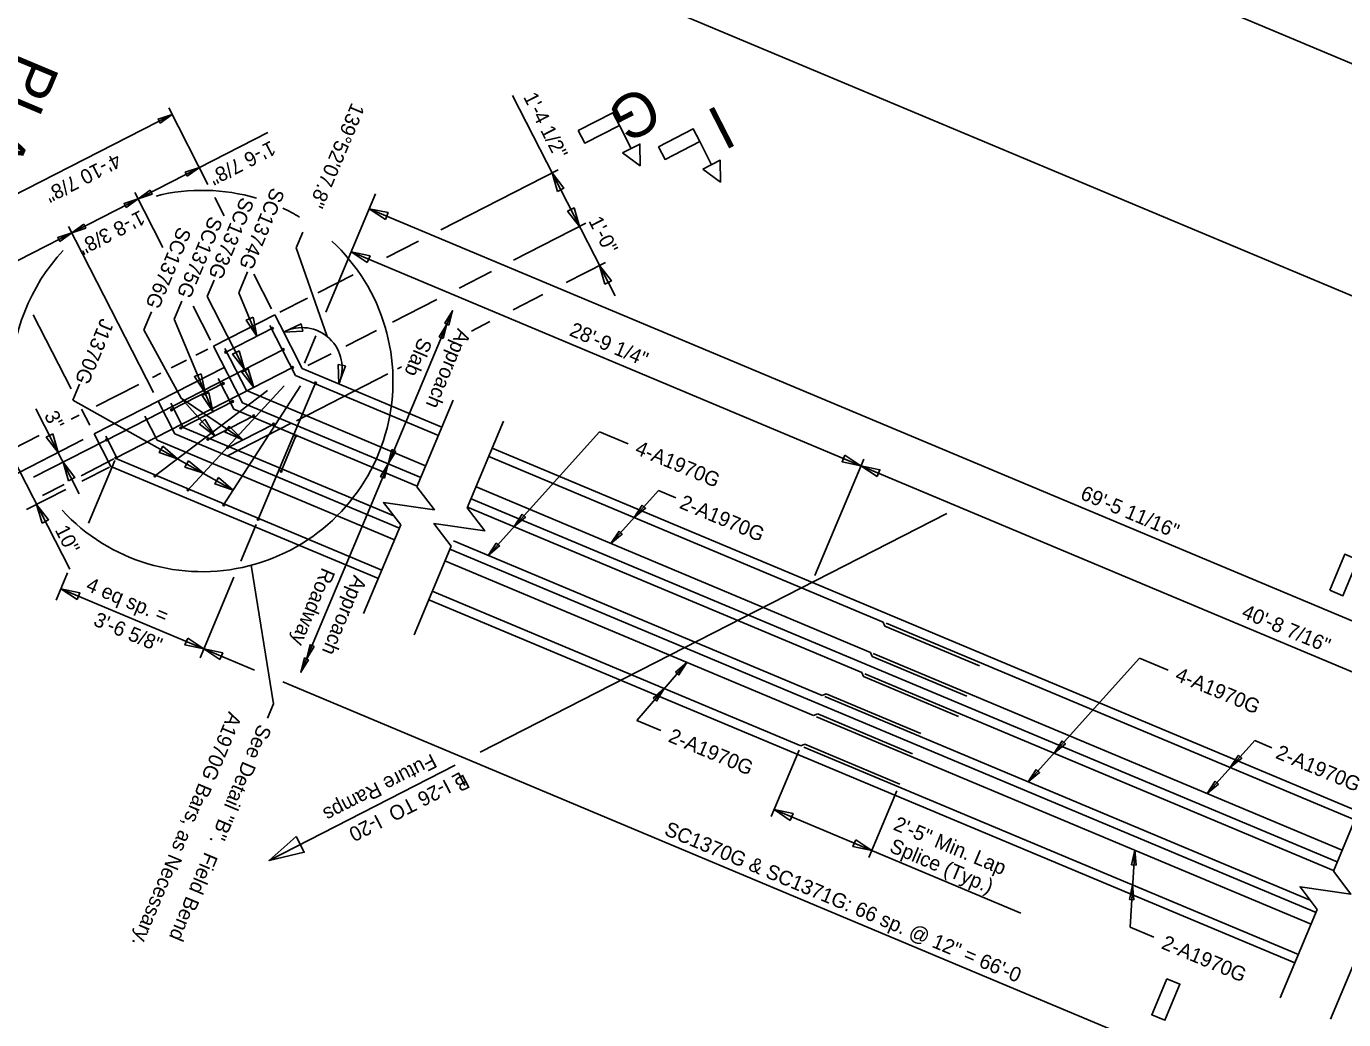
# Model space of a CAD drawing. Extents: x 1968564 to 1968711, y 796599 to 796794.
# Drawn here: x 1968616.17 to 1968661.26, y 796715.41 to 796749.41 of the extents above; entities that cross this region are included whole.
import ezdxf

# ---------------------------------------------------------------- set-up
doc = ezdxf.new("R2010")
doc.units = 0
for name, color, linetype in [('BR_AUTO DIMENSION', 7, 'Continuous'), ('BR_BORDER LINES', 7, 'Continuous'), ('BR_CENTER LINES', 7, 'Continuous'), ('BR_CONCRETE', 7, 'Continuous'), ('BR_REBAR', 7, 'Continuous'), ('BR_TABLE LINES', 7, 'Continuous'), ('BR_TEXT', 7, 'Continuous'), ('Default', 7, 'Continuous'), ('Level 31', 7, 'Continuous')]:
    doc.layers.add(name, color=color, linetype=linetype)

# ---------------------------------------------------------------- blocks, each defined once
blk = doc.blocks.new('B')
at = {"layer": 'BR_AUTO DIMENSION'}
blk.add_lwpolyline([(-0.2, 0.03), (0, 0), (-0.2, -0.03)], close=True, dxfattribs=at)
blk = doc.blocks.new('ARROW')
at = {"layer": 'BR_AUTO DIMENSION', "xscale": 0.625, "yscale": 0.625}
blk.add_blockref('B', (0, 0), dxfattribs=at)
blk = doc.blocks.new('DAH')
at = {"layer": 'BR_AUTO DIMENSION'}
for p in [(-0.125, 0), (0, 0)]:
    blk.add_blockref('ARROW', p, dxfattribs=at)

msp = doc.modelspace()

# ---------------------------------------------------------------- linework, layer by layer
at = {"layer": 'BR_AUTO DIMENSION'}
for p, q in [((1968632.811, 796747.035), (1968636.321, 796740.18)), ((1968621.161, 796746.392), (1968614.613, 796743.039)), ((1968622.387, 796743.998), (1968621.047, 796746.615)), ((1968624.441, 796745.776), (1968618.755, 796742.864)), ((1968630.363, 796742.444), (1968634.378, 796744.5)), ((1968620.849, 796741.833), (1968619.881, 796743.722)), ((1968626.425, 796739.628), (1968628.12, 796743.67)), ((1968622.941, 796742.917), (1968622.618, 796743.547)), ((1968618.755, 796742.864), (1968615.417, 796741.155)), ((1968627.909, 796743.166), (1968679.369, 796721.583)), ((1968620.525, 796736.874), (1968617.613, 796742.56)), ((1968625.638, 796742.358), (1968625.413, 796741.821)), ((1968632.85, 796741.401), (1968635.318, 796742.665)), ((1968625.413, 796741.821), (1968626.472, 796738.787)), ((1968628.499, 796741.49), (1968629.6, 796742.054)), ((1968627.287, 796741.685), (1968644.739, 796734.365)), ((1968623.44, 796740.288), (1968623.742, 796741.007)), ((1968624.568, 796739.74), (1968623.959, 796740.928)), ((1968630.987, 796740.447), (1968632.088, 796741.011)), ((1968634.652, 796740.639), (1968636.001, 796741.329)), ((1968622.362, 796740.156), (1968622.599, 796740.721)), ((1968626.15, 796740.288), (1968627.354, 796740.904)), ((1968623.954, 796737.047), (1968622.362, 796740.156)), ((1968623.44, 796740.288), (1968624.066, 796738.799)), ((1968624.851, 796739.622), (1968625.8, 796740.108)), ((1968628.7, 796739.276), (1968630.224, 796740.056)), ((1968632.837, 796739.709), (1968633.855, 796740.23)), ((1968620.19, 796739.02), (1968620.45, 796739.639)), ((1968621.232, 796739.38), (1968621.491, 796739.998)), ((1968622.47, 796738.666), (1968621.876, 796739.826)), ((1968627.835, 796732.698), (1968630.761, 796739.674)), ((1968617.708, 796736.995), (1968616.406, 796739.537)), ((1968621.232, 796739.38), (1968622.559, 796736.222)), ((1968631.406, 796738.976), (1968632.042, 796739.302)), ((1968620.19, 796739.02), (1968621.467, 796736.679)), ((1968625.693, 796737.883), (1968626.085, 796738.817)), ((1968627.105, 796738.459), (1968628.155, 796738.997)), ((1968622.389, 796738.362), (1968621.972, 796738.148)), ((1968621.653, 796737.985), (1968621.126, 796737.715)), ((1968625.806, 796737.794), (1968626.603, 796738.202)), ((1968620.77, 796737.532), (1968620.493, 796737.391)), ((1968625.415, 796735.909), (1968628.549, 796737.513)), ((1968628.88, 796737.683), (1968629.016, 796737.753)), ((1968614.48, 796737.033), (1968617.659, 796730.824)), ((1968617.766, 796736.612), (1968617.994, 796737.157)), ((1968620.027, 796737.152), (1968618.564, 796736.403)), ((1968623.256, 796733.532), (1968617.766, 796736.612)), ((1968623.584, 796735.252), (1968621.467, 796736.679)), ((1968621.467, 796736.679), (1968622.625, 796735.394)), ((1968629.538, 796733.648), (1968630.781, 796736.61)), ((1968616.495, 796736.316), (1968617.985, 796733.405)), ((1968617.977, 796736.102), (1968617.711, 796735.966)), ((1968618.342, 796735.756), (1968618.06, 796736.307)), ((1968631.262, 796732.925), (1968632.504, 796735.887)), ((1968635.791, 796735.532), (1968631.977, 796731.299)), ((1968636.771, 796735.121), (1968635.791, 796735.532)), ((1968616.605, 796735.4), (1968615.245, 796734.703)), ((1968618.118, 796735.262), (1968615.548, 796733.946)), ((1968618.854, 796735.217), (1968616.417, 796733.97)), ((1968619.171, 796734.598), (1968618.049, 796734.024)), ((1968619.018, 796734.318), (1968618.071, 796733.833)), ((1968619.197, 796734.541), (1968618.3, 796732.404)), ((1968643.163, 796730.607), (1968644.836, 796734.596)), ((1968643.163, 796730.607), (1968644.836, 796734.596)), ((1968644.739, 796734.365), (1968678.747, 796720.102)), ((1968617.469, 796733.727), (1968616.724, 796733.345)), ((1968617.521, 796733.552), (1968616.181, 796732.866)), ((1968637.811, 796733.517), (1968636.179, 796731.706)), ((1968638.402, 796733.269), (1968637.811, 796733.517)), ((1968624.037, 796732.36), (1968623.51, 796731.103)), ((1968625.569, 796727.295), (1968627.835, 796732.698)), ((1968627.717, 796729.306), (1968628.99, 796732.34)), ((1968629.441, 796728.583), (1968630.714, 796731.617)), ((1968617.584, 796730.696), (1968617.193, 796729.764)), ((1968623.279, 796730.553), (1968622.119, 796727.787)), ((1968623.867, 796730.958), (1968624.636, 796726.217)), ((1968622.249, 796728.098), (1968617.355, 796730.15)), ((1968622.249, 796728.098), (1968623.978, 796727.373)), ((1968637.07, 796725.647), (1968638.776, 796727.635)), ((1968654.277, 796727.779), (1968650.463, 796723.546)), ((1968655.258, 796727.368), (1968654.277, 796727.779)), ((1968624.948, 796726.966), (1968669, 796708.489)), ((1968624.636, 796726.217), (1968624.43, 796725.724)), ((1968637.888, 796725.304), (1968637.07, 796725.647)), ((1968658.217, 796724.959), (1968656.585, 796723.148)), ((1968658.808, 796724.711), (1968658.217, 796724.959)), ((1968642.626, 796724.635), (1968641.67, 796722.357)), ((1968660.909, 796720.49), (1968662.151, 796723.452)), ((1968645.968, 796723.233), (1968645.013, 796720.955)), ((1968641.77, 796722.595), (1968650.217, 796719.052)), ((1968653.95, 796718.567), (1968654.111, 796721.203)), ((1968659.088, 796716.149), (1968660.361, 796719.182)), ((1968654.768, 796718.224), (1968653.95, 796718.567)), ((1968660.812, 796715.426), (1968662.084, 796718.459))]:
    msp.add_line(p, q, dxfattribs=at)
for points in [[(1968620.75, 796746.098), (1968621.161, 796746.392), (1968620.682, 796746.231)], [(1968621.682, 796744.279), (1968622.093, 796744.573), (1968621.613, 796744.412)], [(1968634.35, 796743.756), (1968634.165, 796744.391), (1968634.572, 796743.87)], [(1968620.406, 796743.794), (1968619.995, 796743.499), (1968620.475, 796743.661)], [(1968619.585, 796743.205), (1968619.995, 796743.499), (1968619.516, 796743.338)], [(1968634.697, 796743.077), (1968635.105, 796742.556), (1968634.92, 796743.191)], [(1968628.46, 796742.8), (1968627.909, 796743.166), (1968628.556, 796743.03)], [(1968617.316, 796742.043), (1968617.727, 796742.338), (1968617.248, 796742.177)], [(1968618.138, 796742.633), (1968617.727, 796742.338), (1968618.206, 796742.499)], [(1968627.838, 796741.318), (1968627.287, 796741.685), (1968627.935, 796741.549)], [(1968635.973, 796740.585), (1968635.788, 796741.22), (1968636.196, 796740.699)], [(1968623.93, 796739.447), (1968624.066, 796738.799), (1968623.699, 796739.35)], [(1968625.637, 796738.977), (1968624.975, 796738.943), (1968625.577, 796739.219)], [(1968623.452, 796738.302), (1968623.637, 796737.666), (1968623.23, 796738.188)], [(1968627.097, 796737.791), (1968626.869, 796737.17), (1968626.85, 796737.831)], [(1968622.152, 796737.512), (1968622.289, 796736.865), (1968621.922, 796737.416)], [(1968623.769, 796737.683), (1968623.954, 796737.047), (1968623.547, 796737.569)], [(1968622.422, 796736.87), (1968622.559, 796736.222), (1968622.192, 796736.773)], [(1968622.283, 796735.961), (1968622.625, 796735.394), (1968622.097, 796735.793)], [(1968623.115, 796735.719), (1968623.584, 796735.252), (1968622.975, 796735.512)], [(1968617.074, 796735.458), (1968617.26, 796734.822), (1968616.852, 796735.343)], [(1968620.842, 796735.033), (1968621.346, 796734.604), (1968620.719, 796734.815)], [(1968628.823, 796734.859), (1968628.56, 796734.427), (1968628.684, 796734.917)], [(1968644.188, 796734.732), (1968644.739, 796734.365), (1968644.092, 796734.502)], [(1968617.612, 796733.852), (1968617.431, 796734.489), (1968617.836, 796733.965)], [(1968621.726, 796734.537), (1968622.23, 796734.108), (1968621.602, 796734.319)], [(1968628.436, 796733.937), (1968628.56, 796734.427), (1968628.297, 796733.995)], [(1968645.291, 796733.999), (1968644.739, 796734.365), (1968645.387, 796734.229)], [(1968622.752, 796733.961), (1968623.256, 796733.532), (1968622.629, 796733.743)], [(1968616.709, 796732.406), (1968616.524, 796733.041), (1968616.931, 796732.52)], [(1968637.256, 796733.013), (1968636.977, 796732.591), (1968637.367, 796732.913)], [(1968633.143, 796732.705), (1968632.864, 796732.283), (1968633.254, 796732.604)], [(1968636.458, 796732.128), (1968636.179, 796731.706), (1968636.569, 796732.027)], [(1968632.256, 796731.721), (1968631.977, 796731.299), (1968632.368, 796731.621)], [(1968617.906, 796729.784), (1968617.355, 796730.15), (1968618.003, 796730.014)], [(1968621.698, 796728.464), (1968622.249, 796728.098), (1968621.602, 796728.234)], [(1968622.8, 796727.731), (1968622.249, 796728.098), (1968622.897, 796727.961)], [(1968626.022, 796728.183), (1968625.76, 796727.751), (1968625.884, 796728.241)], [(1968625.831, 796727.727), (1968625.569, 796727.295), (1968625.693, 796727.786)], [(1968638.394, 796727.304), (1968638.776, 796727.635), (1968638.507, 796727.206)], [(1968637.624, 796726.407), (1968638.006, 796726.738), (1968637.738, 796726.309)], [(1968651.629, 796724.951), (1968651.35, 796724.53), (1968651.74, 796724.851)], [(1968657.662, 796724.454), (1968657.383, 796724.033), (1968657.773, 796724.354)], [(1968650.742, 796723.968), (1968650.463, 796723.546), (1968650.854, 796723.867)], [(1968656.864, 796723.569), (1968656.585, 796723.148), (1968656.975, 796723.469)], [(1968642.321, 796722.228), (1968641.77, 796722.595), (1968642.417, 796722.458)], [(1968644.561, 796721.559), (1968645.112, 796721.193), (1968644.465, 796721.329)], [(1968654.005, 796720.709), (1968654.111, 796721.203), (1968654.155, 796720.699)], [(1968653.933, 796719.519), (1968654.038, 796720.014), (1968654.083, 796719.51)]]:
    msp.add_lwpolyline(points, close=True, dxfattribs=at)
for points in [[(1968629.538, 796733.648), (1968630.14, 796732.859), (1968628.398, 796733.11), (1968628.99, 796732.34)], [(1968631.262, 796732.925), (1968631.864, 796732.136), (1968630.122, 796732.387), (1968630.714, 796731.617)], [(1968660.909, 796720.49), (1968661.511, 796719.702), (1968659.769, 796719.953), (1968660.361, 796719.182)]]:
    msp.add_lwpolyline(points, dxfattribs=at)
for centre, radius, start, end in [((1968622.193, 796737.267), 6.527, 73.4685, 104.0094), ((1968622.193, 796737.267), 6.527, 59.2916, 65.0137), ((1968622.193, 796737.267), 6.527, 222.6759, 47.1949), ((1968622.193, 796737.267), 6.527, 136.8064, 180.4125), ((1968625.604, 796737.717), 1.378, 336.6203, 117.1148)]:
    msp.add_arc(centre, radius, start, end, dxfattribs=at)
at = {"layer": 'BR_BORDER LINES'}
msp.add_line((1968618.549, 796758.212), (1968696.012, 796725.723), dxfattribs=at)
at = {"layer": 'BR_CENTER LINES'}
for p, q in [((1968647.675, 796732.736), (1968631.701, 796724.557)), ((1968630.846, 796724.119), (1968624.478, 796720.858))]:
    msp.add_line(p, q, dxfattribs=at)
at = {"layer": 'BR_CONCRETE'}
for p, q in [((1968624.674, 796739.532), (1968622.577, 796738.458)), ((1968624.845, 796739.198), (1968624.674, 796739.532)), ((1968625.614, 796737.696), (1968624.845, 796739.198)), ((1968623.569, 796736.52), (1968622.577, 796738.458)), ((1968622.947, 796737.735), (1968618.496, 796735.455)), ((1968630.395, 796735.691), (1968625.614, 796737.696)), ((1968621.249, 796735.46), (1968620.679, 796736.573)), ((1968629.67, 796733.962), (1968623.569, 796736.52)), ((1968625.241, 796735.819), (1968623.058, 796734.702)), ((1968619.066, 796734.343), (1968618.496, 796735.455)), ((1968628.945, 796732.232), (1968621.249, 796735.46)), ((1968661.766, 796722.533), (1968632.119, 796734.968)), ((1968619.066, 796734.343), (1968628.22, 796730.503)), ((1968661.041, 796720.804), (1968631.394, 796733.239)), ((1968660.316, 796719.075), (1968630.669, 796731.51)), ((1968629.943, 796729.78), (1968659.59, 796717.346))]:
    msp.add_line(p, q, dxfattribs=at)
at = {"layer": 'BR_REBAR'}
for p, q in [((1968625.388, 796737.452), (1968624.51, 796739.167)), ((1968624.623, 796739.084), (1968623.026, 796738.266)), ((1968624.993, 796738.361), (1968618.889, 796735.235)), ((1968623.707, 796736.937), (1968622.969, 796738.378)), ((1968625.31, 796737.742), (1968619.206, 796734.616)), ((1968623.276, 796736.304), (1968622.741, 796737.348)), ((1968630.274, 796735.402), (1968625.388, 796737.452)), ((1968620.548, 796733.997), (1968624.428, 796736.947)), ((1968621.117, 796736.265), (1968622.941, 796737.199)), ((1968621.684, 796733.518), (1968624.994, 796737.097)), ((1968622.914, 796733), (1968625.551, 796737.1)), ((1968629.839, 796734.365), (1968623.707, 796736.937)), ((1968624.097, 796732.503), (1968626.08, 796737.23)), ((1968621.542, 796735.676), (1968621.113, 796736.514)), ((1968621.434, 796735.646), (1968623.258, 796736.58)), ((1968620.644, 796735.239), (1968620.224, 796736.059)), ((1968623.98, 796736.088), (1968622.356, 796735.256)), ((1968629.549, 796733.673), (1968623.276, 796736.304)), ((1968628.749, 796732.654), (1968621.542, 796735.676)), ((1968624.66, 796735.803), (1968623.035, 796734.971)), ((1968619.292, 796734.587), (1968618.888, 796735.375)), ((1968628.776, 796731.829), (1968620.644, 796735.239)), ((1968624.881, 796734.146), (1968625.412, 796735.414)), ((1968645.5, 796729.016), (1968631.998, 796734.679)), ((1968628.34, 796730.792), (1968619.292, 796734.587)), ((1968645.065, 796727.979), (1968631.563, 796733.642)), ((1968644.775, 796727.287), (1968631.273, 796732.95)), ((1968643.41, 796726.505), (1968630.789, 796731.798)), ((1968643.119, 796725.813), (1968630.499, 796731.106)), ((1968642.684, 796724.776), (1968630.064, 796730.069)), ((1968645.5, 796729.016), (1968645.557, 796728.878)), ((1968645.557, 796728.878), (1968648.802, 796727.517)), ((1968661.645, 796722.245), (1968645.598, 796728.975)), ((1968645.065, 796727.979), (1968645.122, 796727.84)), ((1968661.21, 796721.208), (1968645.163, 796727.938)), ((1968645.122, 796727.84), (1968648.367, 796726.479)), ((1968644.775, 796727.287), (1968644.832, 796727.149)), ((1968644.832, 796727.149), (1968648.077, 796725.788)), ((1968660.92, 796720.516), (1968644.873, 796727.246)), ((1968643.41, 796726.505), (1968643.548, 796726.561)), ((1968643.548, 796726.561), (1968646.793, 796725.2)), ((1968660.12, 796719.496), (1968643.507, 796726.464)), ((1968643.119, 796725.813), (1968643.258, 796725.87)), ((1968660.146, 796718.672), (1968643.217, 796725.772)), ((1968643.258, 796725.87), (1968646.503, 796724.509)), ((1968642.684, 796724.776), (1968642.823, 796724.832)), ((1968659.711, 796717.634), (1968642.782, 796724.735)), ((1968642.823, 796724.832), (1968646.068, 796723.471))]:
    msp.add_line(p, q, dxfattribs=at)
for centre in [(1968624.595, 796739.07), (1968622.998, 796738.252), (1968624.965, 796738.347), (1968625.282, 796737.727), (1968622.913, 796737.184), (1968626.067, 796737.201), (1968623.23, 796736.566), (1968621.145, 796736.279), (1968623.952, 796736.074), (1968621.462, 796735.66), (1968624.632, 796735.789), (1968618.917, 796735.25), (1968622.384, 796735.27), (1968625.4, 796735.386), (1968619.234, 796734.631), (1968623.063, 796734.985), (1968624.893, 796734.175), (1968620.573, 796734.016), (1968621.705, 796733.541), (1968622.931, 796733.027), (1968624.109, 796732.532)]:
    msp.add_circle(centre, 0.0313, dxfattribs=at)
at = {"layer": 'BR_TABLE LINES'}
for p, q in [((1968636.471, 796746.017), (1968636.876, 796745.226)), ((1968639.22, 796745.46), (1968639.625, 796744.669))]:
    msp.add_line(p, q, dxfattribs=at)
for points in [[(1968635.062, 796745.845), (1968635.284, 796745.409), (1968636.471, 796746.017), (1968636.248, 796746.452)], [(1968637.81, 796745.288), (1968638.033, 796744.853), (1968639.22, 796745.46), (1968638.997, 796745.896)], [(1968636.58, 796745.074), (1968637.18, 796744.633), (1968637.173, 796745.378)], [(1968639.328, 796744.517), (1968639.929, 796744.076), (1968639.922, 796744.821)], [(1968660.786, 796730.108), (1968661.237, 796729.919), (1968661.753, 796731.149), (1968661.302, 796731.338)], [(1968655.206, 796716.804), (1968655.657, 796716.615), (1968655.142, 796715.386), (1968654.691, 796715.575)]]:
    msp.add_lwpolyline(points, close=True, dxfattribs=at)
at = {"layer": 'Default'}
msp.add_lwpolyline([(1968625.409, 796721.672), (1968624.478, 796720.858), (1968625.683, 796721.138)], close=True, dxfattribs=at)
at = {"layer": 'Level 31'}
msp.add_lwpolyline([(1968619.541, 796765.748), (1968563.846, 796632.955), (1968644.997, 796598.919), (1968700.693, 796731.712)], close=True, dxfattribs=at)

# ---------------------------------------------------------------- block references
at = {"layer": 'BR_TEXT', "xscale": 4.00000005, "yscale": -4.00000005, "rotation": 67.24601034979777}
msp.add_blockref('DAH', (1968630.761, 796739.674), dxfattribs=at)

# ---------------------------------------------------------------- texts
at = {"layer": 'BR_AUTO DIMENSION'}
for s, rotation, p in [('1\'-4 1/2"', 297.1148, (1968633.169, 796746.993)), ('139%%d52\'07.8"', 247.246, (1968627.31, 796746.821)), ('1\'-6 7/8"', 207.1148, (1968624.542, 796745.508)), ('4\'-10 7/8"', 207.1148, (1968619.257, 796745.083)), ('1\'-8 3/8"', 207.1148, (1968620.069, 796743.128)), ('1\'-0"', 297.1148, (1968635.398, 796742.751)), ('28\'-9 1/4"', 337.246, (1968634.723, 796738.838)), ('3"', 297.1148, (1968616.768, 796736.09)), ('69\'-5 11/16"', 337.246, (1968652.214, 796733.243)), ('10"', 297.1148, (1968617.134, 796732.176)), ('4 eq sp. =', 337.246, (1968618.175, 796730.11)), ('3\'-6 5/8"', 337.246, (1968618.433, 796728.917)), ('40\'-8 7/16"', 337.246, (1968657.735, 796729.186)), ('Future Ramps', 207.1148, (1968630.049, 796724.522)), ('L I-26 TO  I-20', 207.1148, (1968631.032, 796723.902)), ('B', 207.1148, (1968631.17, 796723.822)), (' SC1370G & SC1371G: 66 sp. @ 12" = 66\'-0', 337.246, (1968637.802, 796721.817)), ('2\'-5" Min. Lap ', 337.246, (1968645.813, 796721.921)), ('Splice (Typ.)', 337.246, (1968645.678, 796721.164))]:
    msp.add_text(s, height=0.5, rotation=rotation, dxfattribs=at).set_placement(p)
at = {"layer": 'BR_TEXT'}
for s, height, rotation, p in [('PLAN - SLEEPER SLAB', 1.5, 247.246, (1968615.94, 796748.544)), ('G', 1.5, 207.1148, (1968637.357, 796747.41)), ('I', 1.5, 207.1148, (1968639.875, 796746.734)), (' SC1374G', 0.4999, 247.246, (1968624.641, 796744.093)), (' SC1373G', 0.4999, 247.246, (1968623.594, 796743.76)), (' SC1375G', 0.4999, 247.246, (1968622.517, 796743.112)), (' SC1376G', 0.4999, 247.246, (1968621.444, 796742.75)), ('J1370G', 0.4999, 247.246, (1968618.727, 796739.442)), ('Slab', 0.4999, 247.246, (1968629.617, 796738.788)), ('Approach', 0.4999, 247.246, (1968630.939, 796739.095)), ('4-A1970G', 0.4999, 337.246, (1968636.971, 796734.785)), ('2-A1970G', 0.4999, 337.246, (1968638.493, 796732.93)), (' Roadway', 0.4999, 247.246, (1968626.37, 796731.081)), ('Approach', 0.4999, 247.246, (1968627.383, 796730.653)), ('4-A1970G', 0.4999, 337.246, (1968655.457, 796727.032)), ('A1970G Bars, as Necessary.', 0.49995, 247.246, (1968623.103, 796725.977)), ('See Detail "B".  Field Bend ', 0.49995, 247.246, (1968624.118, 796725.551)), ('2-A1970G', 0.4999, 337.246, (1968638.11, 796724.934)), ('2-A1970G', 0.4999, 337.246, (1968658.898, 796724.371)), ('2-A1970G', 0.4999, 337.246, (1968654.99, 796717.854))]:
    msp.add_text(s, height=height, rotation=rotation, dxfattribs=at).set_placement(p)

doc.saveas('drawing.dxf')
